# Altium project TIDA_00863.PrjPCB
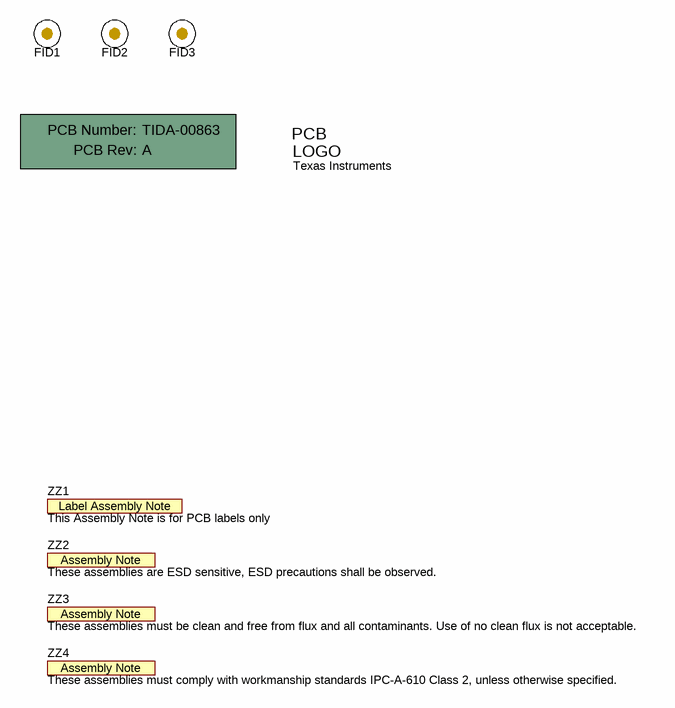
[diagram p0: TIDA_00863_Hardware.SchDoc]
CopyrightYear: 2015; PCB_Layout: Jason Liu; PCB_Rev: A; PRJ_Customer: Public Release; PRJ_Engineer: Jason Liu; PRJ_Number: TIDA-00863; PRJ_Title: TIDA-00863; SCH_Rev: A; TechSupport: http://www.ti.com/support; TID: TIDA-00863
2 sheets, 37 parts. Net scope: global (net labels, ports and power ports of the same name join across sheets).
Board file: TIDA_00863_PCB.PcbDoc
Sheets:
  TIDA_00863_Hardware.SchDoc
  TIDA_00863_SCH.SchDoc

## Sheet TIDA_00863_Hardware.SchDoc
size 431 x 279 mm; Date: Not shown in title block; ApprovedBy: Not shown in title block; CheckedBy: Not shown in title block; Author: Not shown in title block; CompanyName: Not shown in title block; Engineer: Not shown in title block; Organization: Not shown in title block; Address1: Not shown in title block; Address2: Not shown in title block; Address3: Not shown in title block; Address4: Not shown in title block; DocumentNumber: 1; Revision: Use project parameter SCH_Rev; SheetNumber: 3; SheetTotal: 3; PageSetup: Record=PageOptions¦CenterHorizontal=True¦CenterVertical=True¦PrintScale=1.00¦XCorrection=1.00¦YCorrection=1.00¦PrintKind=0¦BorderSize=5000000¦LeftOffset=0¦BottomOffset=0¦Orientation=2¦PaperLength=1000¦PaperWidth=1000¦Scale=100¦PaperSource=15¦PrintQuality=600¦MediaType=1¦DitherType=10¦PaperKind=Letter¦PrintScaleMode=1

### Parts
!PCB1  Printed Circuit Board  (value not drawn)  (mechanical)
FID1  Fiducial  [Fiducial10-20]  (value not drawn)
FID2  Fiducial  [Fiducial10-20]  (value not drawn)
FID3  Fiducial  [Fiducial10-20]  (value not drawn)
Logo1  Texas Instruments  [TI_Stacked_Overlay_Small]  (no BOM)
ZZ1  This Assembly Note is for PCB labels only  [AssemblyNoteLabel]  (no BOM)
ZZ2  These assemblies are ESD sensitive, ESD precautions shall be observed.  [AssemblyNote]  (no BOM)
ZZ3  These assemblies must be clean and free from flux and all contaminants. Use of no clean flux is not acceptable.  [AssemblyNote]  (no BOM)
ZZ4  These assemblies must comply with workmanship standards IPC-A-610 Class 2, unless otherwise specified.  [AssemblyNote]  (no BOM)

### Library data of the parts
!PCB1 = PCB: Manufacturer: Any; PartNumber: TIDA-00863; SymbolCreator: a0412235
FID1-FID3 = Fiducial: Fiducial mark.  There is nothing to buy or mount.; SymbolCreator: codlsc
Logo1 = TI_Logo: Texas Instrument Corporate Signature; SymbolCreator: codlsc
ZZ1 = AssemblyNoteLabel: SymbolCreator: a0412235
ZZ2-ZZ4 = AssemblyNote: SymbolCreator: codlsc

## Sheet TIDA_00863_SCH.SchDoc
size 431 x 279 mm; Date: Not shown in title block; ApprovedBy: Not shown in title block; CheckedBy: Not shown in title block; Author: Not shown in title block; CompanyName: Not shown in title block; Engineer: Not shown in title block; Organization: Not shown in title block; Address1: Not shown in title block; Address2: Not shown in title block; Address3: Not shown in title block; Address4: Not shown in title block; DocumentNumber: 1; Revision: Use project parameter SCH_Rev; SheetNumber: 2; SheetTotal: 3; PageSetup: Record=PageOptions¦CenterHorizontal=True¦CenterVertical=True¦PrintScale=0.64¦XCorrection=1.00¦YCorrection=1.00¦PrintKind=0¦BorderSize=5000000¦LeftOffset=0¦BottomOffset=0¦Orientation=2¦PaperLength=1000¦PaperWidth=1000¦Scale=100¦PaperSource=15¦PrintQuality=600¦MediaType=1¦DitherType=10¦PrintScaleMode=1¦PaperKind=Letter; EVM_orderable: N/A
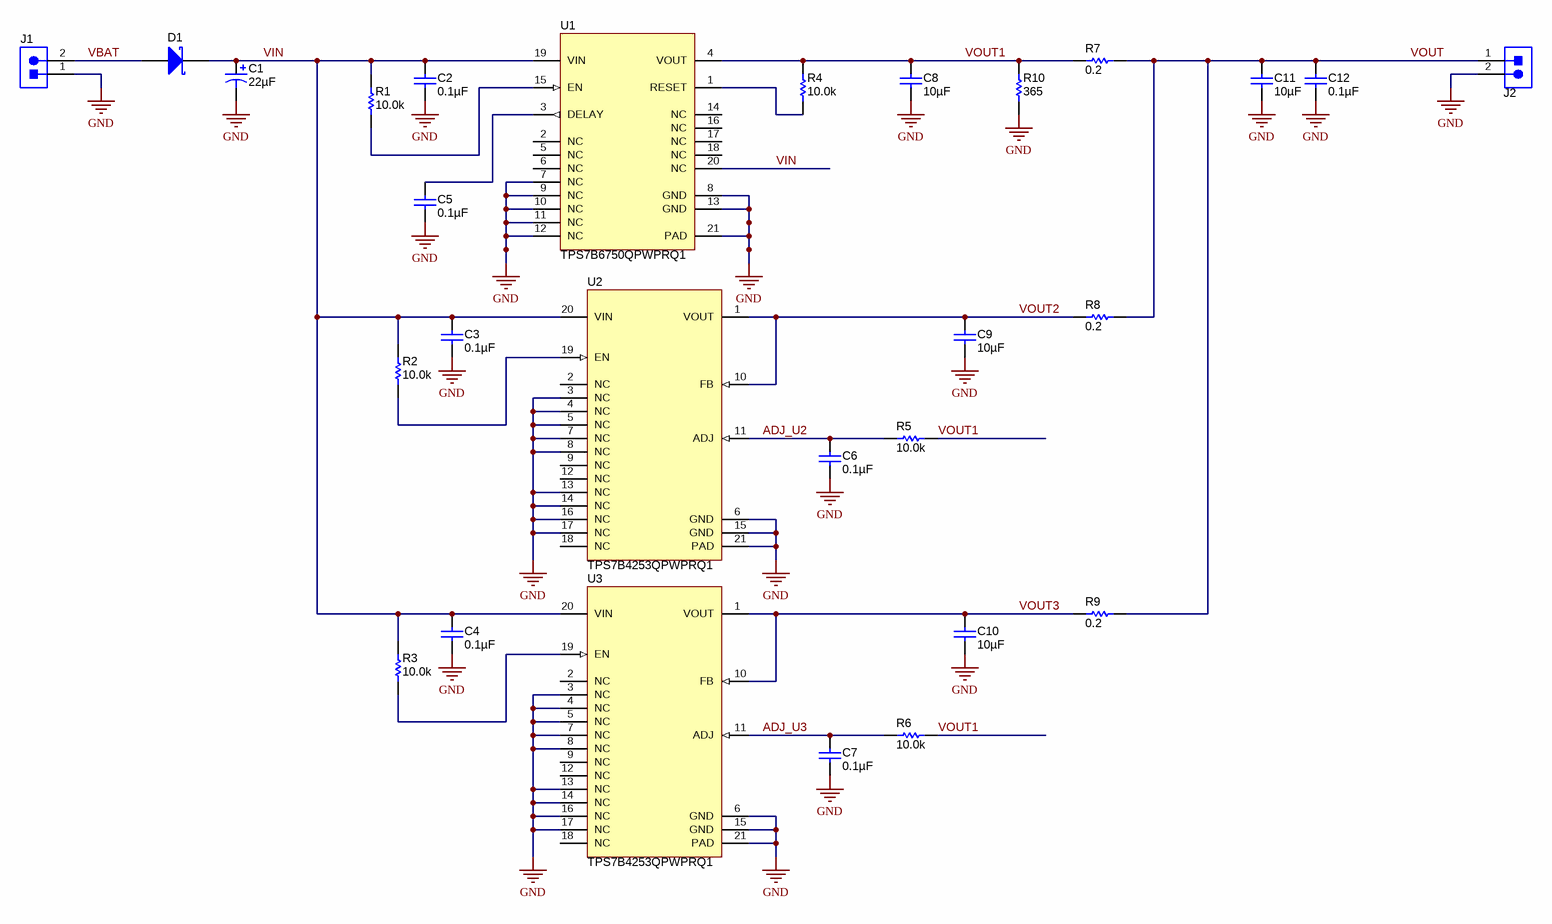
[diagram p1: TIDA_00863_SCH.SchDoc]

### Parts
C1  ValueDisplayed: 22µF  [SM_RADIAL_D]  (hidden comment: EEE-FK1H220P)
C2  ValueDisplayed: 0.1µF  [0603]  (hidden comment: GCM188R71H104KA57D)
C3  ValueDisplayed: 0.1µF  [0603]  (hidden comment: GCM188R71H104KA57D)
C4  ValueDisplayed: 0.1µF  [0603]  (hidden comment: GCM188R71H104KA57D)
C5  ValueDisplayed: 0.1µF  [0603]  (hidden comment: GCM188R71H104KA57D)
C6  ValueDisplayed: 0.1µF  [0603]  (hidden comment: GCM188R71H104KA57D)
C7  ValueDisplayed: 0.1µF  [0603]  (hidden comment: GCM188R71H104KA57D)
C8  ValueDisplayed: 10µF  [1206_190]  (hidden comment: GCM31CR71C106KA64L)
C9  ValueDisplayed: 10µF  [1206_190]  (hidden comment: GCM31CR71C106KA64L)
C10  ValueDisplayed: 10µF  [1206_190]  (hidden comment: GCM31CR71C106KA64L)
C11  ValueDisplayed: 10µF  [1206_190]  (hidden comment: GCM31CR71C106KA64L)
C12  ValueDisplayed: 0.1µF  [0603]  (hidden comment: GCM188R71H104KA57D)
D1  B260A-13-F  [SMA]  (value not drawn)
J1  ED555/2DS  [TERM_BLK_ED555-2DS]  (value not drawn)
J2  ED555/2DS  [TERM_BLK_ED555-2DS]  (value not drawn)
R1  ValueDisplayed: 10.0k  [0603]  (hidden comment: CRCW060310K0FKEA)
R2  ValueDisplayed: 10.0k  [0603]  (hidden comment: CRCW060310K0FKEA)
R3  ValueDisplayed: 10.0k  [0603]  (hidden comment: CRCW060310K0FKEA)
R4  ValueDisplayed: 10.0k  [0603]  (hidden comment: CRCW060310K0FKEA)
R5  ValueDisplayed: 10.0k  [0603]  (hidden comment: CRCW060310K0FKEA)
R6  ValueDisplayed: 10.0k  [0603]  (hidden comment: CRCW060310K0FKEA)
R7  ValueDisplayed: 0.2  [2512]  (hidden comment: WSL2512R2000FEA)
R8  ValueDisplayed: 0.2  [2512]  (hidden comment: WSL2512R2000FEA)
R9  ValueDisplayed: 0.2  [2512]  (hidden comment: WSL2512R2000FEA)
R10  ValueDisplayed: 365  [0805_HV]  (hidden comment: CRCW0805365RFKEA)
U1  TPS7B6750QPWPRQ1  [PWP0020D_N]
U2  TPS7B4253QPWPRQ1  [PWP0020D_N]
U3  TPS7B4253QPWPRQ1  [PWP0020D_N]

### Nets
GND: C1.2(-) C2.2 C3.2 C4.2 C5.1 C6.2 C7.2 C8.2 C9.2 C10.2 C11.2 C12.2 J1.1 J2.2 R10.1 U1.7(NC) U1.8(GND) U1.9(NC) U1.10(NC) U1.11(NC) U1.12(NC) U1.13(GND) U1.21(PAD) U2.3(NC) U2.4(NC) U2.5(NC) U2.6(GND) U2.7(NC) U2.8(NC) U2.13(NC) U2.14(NC) U2.15(GND) U2.16(NC) U2.17(NC) U2.21(PAD) U3.3(NC) U3.4(NC) U3.5(NC) U3.6(GND) U3.7(NC) U3.8(NC) U3.13(NC) U3.14(NC) U3.15(GND) U3.16(NC) U3.17(NC) U3.21(PAD)
ADJ_U2: C6.1 R5.1 U2.11(ADJ)
ADJ_U3: C7.1 R6.1 U3.11(ADJ)
VBAT: D1.2(A) J1.2
VIN: C1.1(+) C2.1 C3.1 C4.1 D1.1(K) R1.2 R2.2 R3.2 U1.19(VIN) U1.20(NC) U2.20(VIN) U3.20(VIN)
VOUT: C11.1 C12.1 J2.1 R7.2 R8.1 R9.1
VOUT1: C8.1 R4.2 R5.2 R6.2 R7.1 R10.2 U1.4(VOUT)
VOUT2: C9.1 R8.2 U2.1(VOUT) U2.10(FB)
VOUT3: C10.1 R9.2 U3.1(VOUT) U3.10(FB)
NetC5_2: C5.2 U1.3(DELAY)
NetR1_1: R1.1 U1.15(EN)
NetR2_1: R2.1 U2.19(EN)
NetR3_1: R3.1 U3.19(EN)
NetR4_1: R4.1 U1.1(RESET)

Not connected (* = marked no-connect by the designer): U1 2(NC) 5(NC) 6(NC) 14(NC) 16(NC) 17(NC) 18(NC); U2 2(NC) 9(NC) 12(NC) 18(NC); U3 2(NC) 9(NC) 12(NC) 18(NC)

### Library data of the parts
C1 = EEE-FK1H220P: CAP, AL, 22 µF, 50 V, +/- 20%, 0.88 ohm, SMD; Manufacturer: Panasonic; Polarized: Y; CompType: Capacitor; Value: 22uF; U/M: EA; Cap_F: 0.000022; Tolerance_%: 20; VDC_V: 50; Value2: 50V; ESR_ohm: 0.88; IRMS_A: 0.165; TaMin_C: -55; TaMax_C: 105; Cap_Case: D
C2-C7 C12 = GCM188R71H104KA57D: CAP, CERM, 0.1 µF, 50 V, +/- 10%, X7R, 0603; Manufacturer: MuRata; Polarized: N; CompType: Capacitor; Value: 0.1uF; U/M: EA; Cap_F: 0.0000001; Tolerance_%: 10; ESR_ohm: 0.02; Value1: 0.02 ohm; VDC_V: 50; Value2: 50V; IRMS_A: 1.84; TaMin_C: -55; TaMax_C: 125
C8-C11 = GCM31CR71C106KA64L: CAP, CERM, 10 µF, 16 V, +/- 10%, X7R, AEC-Q200 Grade 1, 1206_190; Manufacturer: MuRata; Polarized: N; CompType: Capacitor; Value: 10uF; U/M: EA; Cap_F: 0.00001; Tolerance_%: 10; Value1: Unknown; VDC_V: 16; Value2: 16V; TaMin_C: -55; TaMax_C: 125; Cap_Case: 1206; AEC Category: Q200; AEC Qualified: Y; AEC Grade: 1
D1 = B260A-13-F: Diode, Schottky, 60 V, 2 A, SMA; Manufacturer: Diodes Inc.; U/M: EA; Vf_V: 0.7; Value: 60V; Value1: 2A; Value2: 0.7V; Io_A: 2; Vr_V: 60; TJmax_C: 150; RJC_CperW: 20
J1 J2 = ED555/2DS: Terminal Block, 6A, 3.5mm Pitch, 2-Pos, TH; Manufacturer: On-Shore Technology; SymbolCreator: a0412235; CompType: Connector; U/M: EA
R1-R3 R5 R6 = CRCW060310K0FKEA: RES, 10.0 k, 1%, 0.1 W, 0603; Manufacturer: Vishay-Dale; CompType: Resistor; Value: 10.0k; Res_ohm: 10000; Value_Code: 10k0; Tolerance_%: 1; Power_W: 0.1; Value2: 0.1W; VDC_V: 75; TempCo: 100 ppm/C; EIA_Code: E96; U/M: EA; AEC Category: Q200
R4 = CRCW060310K0FKEA: RES, 10.0 k, 1%, 0.1 W, 0603; Manufacturer: Vishay-Dale; CompType: Resistor; Value: 10.0k; Res_ohm: 10000; Value_Code: 10k0; Tolerance_%: 1; Power_W: 0.1; Value2: 0.1W; VDC_V: 75; TempCo: 100 ppm/C; EIA_Code: E96; U/M: EA
R7-R9 = WSL2512R2000FEA: RES, 0.2, 1%, 1 W, 2512; Manufacturer: Vishay-Dale; CompType: Resistor; Value: 0.2; Value_Code: R200; Tolerance_%: 1; Value2: 1W; VDC_V: 0.45; TempCo: 75 ppm/C; EIA_Code: E96; U/M: EA; AEC Category: Q200
R10 = CRCW0805365RFKEA: RES, 365, 1%, 0.125 W, 0805; Manufacturer: Vishay-Dale; CompType: Resistor; Value: 365; Value_Code: 365R; Tolerance_%: 1; Power_W: 0.125; Value2: 0.125W; VDC_V: 150; TempCo: 100 ppm/C; EIA_Code: E96; U/M: EA; AEC Category: Q200
U1 = TPS7B6750QPWPRQ1: 450-mA High-Voltage Ultra-Low IQ Low-Dropout Regulator, PWP0020D; Manufacturer: Texas Instruments; SymbolCreator: Altium; CompType: IC; U/M: EA
U2 U3 = TPS7B4253QPWPRQ1: 300mA Low Dropout Voltage Tracking LDO, PWP0020D; Manufacturer: Texas Instruments; SymbolCreator: a0799628; CompType: IC; U/M: EA

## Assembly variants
001: not fitted FID1 FID2 FID3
